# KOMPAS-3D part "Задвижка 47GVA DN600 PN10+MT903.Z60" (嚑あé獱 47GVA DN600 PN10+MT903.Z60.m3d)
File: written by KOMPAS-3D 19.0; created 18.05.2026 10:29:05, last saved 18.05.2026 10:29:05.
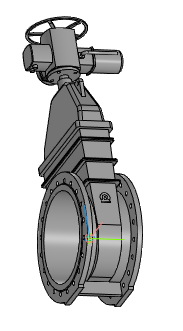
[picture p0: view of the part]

Document properties: Автор: Энергия; Полное имя файла: ..\Задвижка 47GVA DN50_DN1000+MT903.Z\Задвижка 47GVA DN600 PN10+MT903.Z60.a3d

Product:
- Part/product: Задвижка 47GVA DN600 PN10+MT903.Z60
    Масса: 1125.99
  - Body: Электропривод MT903.Z45-60
      Масса: 170.293
  - Body: Задвижка 47GVA DN600 PN10 без исполнительного механизма
      Масса: 955.696

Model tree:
1. Операция без истории:1
2. Операция без истории:2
